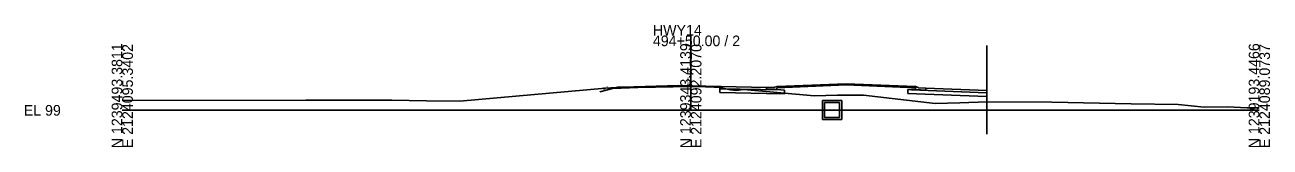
# Model space of a CAD drawing. Extents: x -26 to 303, y -10 to 11521.
# Drawn here: x -25.7 to 302.8, y 5990.3 to 6022.5 of the extents above; entities that cross this region are included whole.
import ezdxf

# ---------------------------------------------------------------- set-up
doc = ezdxf.new("R2010")
doc.units = 0
for name, color, linetype in [('TS_CURB_GUTTER', 7, 'Continuous'), ('XS_CELL', 7, 'Continuous'), ('XS_P_CONCRETE', 7, 'Continuous'), ('XS_P_FINISHED_GRADE', 7, 'Continuous'), ('XS_P_SUBGRADE_GRANULAR', 7, 'Continuous'), ('XS_P_SUBGRADE_LEVELING', 7, 'Continuous'), ('XS_P_SUBGRADE_PAVEMENT', 7, 'Continuous'), ('XS_P_TX_FS_BS', 7, 'Continuous'), ('XS_PLAN_BUTT_SECTION', 7, 'Continuous'), ('XS_X_DRAINAGE', 7, 'Continuous'), ('XS_X_GROUND', 7, 'Continuous'), ('XS_X_GROUND_TX', 7, 'Continuous')]:
    doc.layers.add(name, color=color, linetype=linetype)

msp = doc.modelspace()

# ---------------------------------------------------------------- linework, layer by layer
at = {"layer": 'TS_CURB_GUTTER'}
for points in [[(170, 6006.02), (169.99, 6005.52), (172.74, 6005.46), (172.77, 6006.28), (172.77, 6006.28), (172.76, 6006.29), (172.76, 6006.29), (172.75, 6006.29), (172.06, 6006.08), (172.03, 6006.06), (172.01, 6006.03), (172, 6006), (172, 6005.98), (170, 6006.02)], [(212.01, 6005.85), (212, 6005.35), (209.25, 6005.46), (209.27, 6006.28), (209.27, 6006.28), (209.27, 6006.29), (209.28, 6006.29), (209.28, 6006.29), (209.96, 6006.04), (209.99, 6006.02), (210.01, 6005.99), (210.02, 6005.95), (210.02, 6005.93), (212.01, 6005.85)]]:
    msp.add_lwpolyline(points, dxfattribs=at)
at = {"layer": 'XS_CELL'}
for p, q in [((150, 6000), (150, 6019.72)), ((0, 6000), (150, 6000)), ((150, 6000), (300, 6000))]:
    msp.add_line(p, q, dxfattribs=at)
at = {"layer": 'XS_P_CONCRETE'}
for p, q in [((172.76, 6005.94), (191.02, 6006.68)), ((172.77, 6006.28), (191.02, 6007.01)), ((209.27, 6006.28), (191.02, 6007.01)), ((209.26, 6005.95), (191.02, 6006.68))]:
    msp.add_line(p, q, dxfattribs=at)
at = {"layer": 'XS_P_FINISHED_GRADE'}
for p, q in [((130, 6005.9), (126, 6004.9)), ((136, 6006.14), (130, 6005.9)), ((150, 6006.42), (136, 6006.14)), ((150, 6006.42), (170, 6006.02)), ((212.01, 6005.85), (228.06, 6005.21))]:
    msp.add_line(p, q, dxfattribs=at)
at = {"layer": 'XS_P_SUBGRADE_GRANULAR'}
for p, q in [((136, 6006.01), (129.4, 6005.75)), ((157.68, 6004.68), (157.68, 6005.68)), ((157.68, 6004.68), (169.97, 6004.43)), ((169.97, 6004.43), (174.74, 6004.34)), ((173.79, 6005.36), (174.74, 6005.34)), ((174.74, 6004.34), (174.74, 6005.34)), ((207.27, 6004.46), (207.27, 6005.46)), ((207.27, 6005.46), (208.22, 6005.42)), ((207.27, 6004.46), (227.99, 6003.63))]:
    msp.add_line(p, q, dxfattribs=at)
at = {"layer": 'XS_P_SUBGRADE_LEVELING'}
for p, q in [((150, 6006.29), (136, 6006.01)), ((136, 6006.01), (136, 6006.14)), ((150, 6006.29), (157.68, 6006.14)), ((157.68, 6006.14), (157.68, 6006.26))]:
    msp.add_line(p, q, dxfattribs=at)
at = {"layer": 'XS_P_SUBGRADE_PAVEMENT'}
for p, q in [((157.68, 6005.68), (157.68, 6006.26)), ((157.68, 6005.68), (173.79, 6005.36)), ((172.74, 6005.46), (173.74, 6005.44)), ((173.74, 6005.44), (173.79, 6005.36)), ((208.27, 6005.5), (208.22, 6005.42)), ((208.22, 6005.42), (228.03, 6004.63)), ((208.27, 6005.5), (209.25, 6005.46))]:
    msp.add_line(p, q, dxfattribs=at)
at = {"layer": 'XS_PLAN_BUTT_SECTION'}
msp.add_line((228.06, 5993.71), (228.06, 6017.12), dxfattribs=at)
at = {"layer": 'XS_X_DRAINAGE'}
for p, q in [((184.73, 6002.62), (189.81, 6002.62)), ((184.73, 5997.54), (184.73, 6002.62)), ((189.81, 5997.54), (189.81, 6002.62)), ((185.27, 5998.08), (185.27, 6002.08)), ((185.27, 6002.08), (189.27, 6002.08)), ((189.27, 5998.08), (189.27, 6002.08)), ((184.73, 5997.54), (189.81, 5997.54)), ((185.27, 5998.08), (189.27, 5998.08))]:
    msp.add_line(p, q, dxfattribs=at)
at = {"layer": 'XS_X_GROUND'}
for p, q in [((89.08, 6002.38), (127.45, 6005.84)), ((127.45, 6005.84), (130.28, 6006.06)), ((130.28, 6006.06), (130.7, 6006.07)), ((130.7, 6006.07), (134.98, 6006.16)), ((134.98, 6006.16), (143.83, 6006.48)), ((143.83, 6006.48), (146.75, 6006.57)), ((146.75, 6006.57), (150, 6006.42)), ((150, 6006.42), (154.54, 6006.2)), ((154.54, 6006.2), (157.68, 6006.05)), ((157.68, 6006.05), (160.46, 6005.4)), ((0, 6002.55), (48.39, 6002.68)), ((48.39, 6002.68), (71.11, 6002.66)), ((71.11, 6002.66), (80.23, 6002.51)), ((80.23, 6002.51), (89.08, 6002.38)), ((160.46, 6005.4), (161.97, 6005.24)), ((161.97, 6005.24), (164.02, 6005.46)), ((164.02, 6005.46), (182.57, 6003.79)), ((182.57, 6003.79), (188.69, 6004.04)), ((188.69, 6004.04), (195.52, 6004)), ((195.52, 6004), (214.44, 6001.82)), ((214.44, 6001.82), (220.96, 6001.99)), ((220.96, 6001.99), (228.19, 6002.24)), ((228.19, 6002.24), (245.29, 6002.13)), ((245.29, 6002.13), (266.16, 6001.74)), ((266.16, 6001.74), (278.57, 6001.57)), ((278.57, 6001.57), (285.43, 6000.85)), ((285.43, 6000.85), (291.64, 6000.94)), ((291.64, 6000.94), (296.76, 6000.68)), ((296.76, 6000.68), (300, 6000.64))]:
    msp.add_line(p, q, dxfattribs=at)

# ---------------------------------------------------------------- texts
at = {"layer": 'XS_CELL'}
for s, p in [('HWY14', (140, 6019.72)), ('494+50.00 / 2', (140, 6016.92)), ('EL 99', (-26, 5998.6))]:
    msp.add_text(s, height=2.8, dxfattribs=at).set_placement(p)
for s, p in [('N 1239493.3811', (0, 5990)), ('E 2124095.3402', (2.8, 5990)), ('N 1239343.4139', (150, 5990)), ('E 2124092.2070', (152.8, 5990)), ('N 1239193.4466', (300, 5990)), ('E 2124089.0737', (302.8, 5990))]:
    msp.add_text(s, height=2.8, rotation=90, dxfattribs=at).set_placement(p)
at = {"layer": 'XS_P_TX_FS_BS'}
msp.add_text('4:1', height=0.8, rotation=14.0362, dxfattribs=at).set_placement((126.88, 6005.29))
at = {"layer": 'XS_X_GROUND_TX'}
msp.add_text('105.42', height=1, rotation=90, dxfattribs=at).set_placement((150, 6006.52))

doc.saveas('drawing.dxf')
